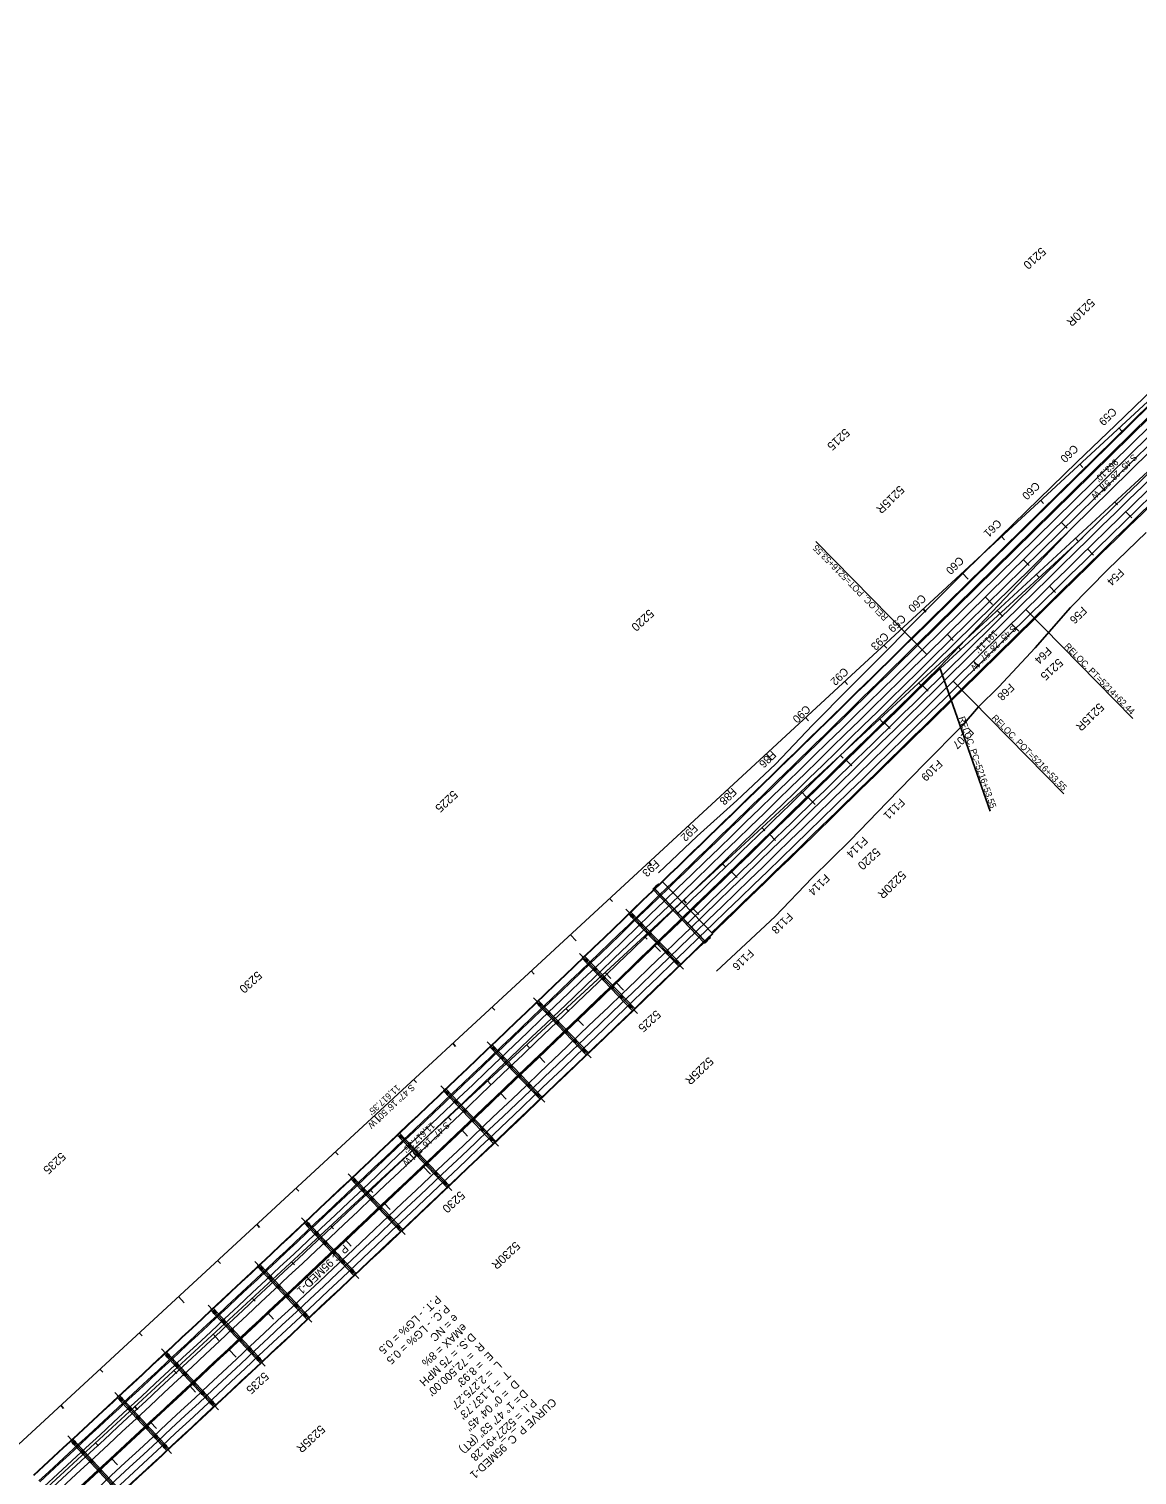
# Model space of a CAD drawing. Extents: x 2160877 to 2175861, y 601747 to 617724.
# Drawn here: x 2167267 to 2169344, y 609138 to 611848 of the extents above; entities that cross this region are included whole.
import ezdxf

# ---------------------------------------------------------------- set-up
doc = ezdxf.new("R2010")
doc.units = 0
for name, color, linetype in [('BR_CENTER LINES', 7, 'Continuous'), ('BR_CONCRETE', 7, 'Continuous'), ('RD_HC_Cl', 7, 'Continuous'), ('RD_HC_CL_Rel', 7, 'Continuous'), ('RD_HC_Data_Rel', 7, 'Continuous'), ('RD_HC_Data_Tic', 7, 'Continuous'), ('RD_HC_Data_Tic_Rel', 7, 'Continuous'), ('RD_HC_TX_Rel_Sta50', 7, 'Continuous'), ('RD_HC_TX_Rel_StaOther', 7, 'Continuous'), ('RD_HC_TX_StaOther', 7, 'Continuous'), ('RD_PD_CstnLmt', 7, 'Continuous'), ('RD_PD_CstnLmt_TX', 7, 'Continuous'), ('RD_PD_Final_LnLine', 7, 'Continuous'), ('RD_PD_Final_TrvlWay', 7, 'Continuous'), ('RD_PD_GR', 7, 'Continuous'), ('RD_PD_MedBWall', 7, 'Continuous')]:
    doc.layers.add(name, color=color, linetype=linetype)

msp = doc.modelspace()

# ---------------------------------------------------------------- linework, layer by layer
at = {"layer": 'BR_CENTER LINES'}
for p, q in [((2168386, 610198.5), (2168494.3, 610086.1)), ((2168299.5, 610115.4), (2168407.8, 610002.8)), ((2168213, 610032.5), (2168321, 609919.7)), ((2168126.4, 609949.7), (2168234.2, 609836.7)), ((2168039.6, 609867), (2168147.2, 609753.9)), ((2167964.2, 609772.3), (2168060.1, 609671.2)), ((2167865.6, 609702.1), (2167972.8, 609588.6)), ((2167778.4, 609619.9), (2167885.5, 609506.2)), ((2167691, 609537.8), (2167797.9, 609424)), ((2167603.6, 609455.9), (2167710.3, 609341.9)), ((2167515.9, 609374.1), (2167622.5, 609259.9)), ((2167428.2, 609292.4), (2167534.5, 609178.1)), ((2167340.3, 609210.9), (2167446.5, 609096.4))]:
    msp.add_line(p, q, dxfattribs=at)
at = {"layer": 'BR_CONCRETE'}
for p, q in [((2168436.5, 610235.6), (2168533.7, 610134.9)), ((2168439, 610238), (2168536.2, 610137.3)), ((2168439.6, 610236.4), (2168534.7, 610137.9)), ((2168447.3, 610246), (2168448.3, 610244.9)), ((2168454, 610250.3), (2168549, 610151.9)), ((2168543.4, 610146.4), (2168544.5, 610145.3))]:
    msp.add_line(p, q, dxfattribs=at)
for points in [[(2168394.9, 610193.2), (2168390.9, 610189.4), (2168485.4, 610091.4), (2168489.3, 610095.2)], [(2168308.4, 610110.1), (2168304.5, 610106.3), (2168398.8, 610008.1), (2168402.8, 610011.9)], [(2168221.9, 610027.1), (2168217.9, 610023.3), (2168312.1, 609925), (2168316.1, 609928.8)], [(2168135.3, 609944.3), (2168131.3, 609940.5), (2168225.3, 609842), (2168229.3, 609845.8)], [(2168048.5, 609861.7), (2168044.5, 609857.9), (2168138.3, 609759.2), (2168142.3, 609763)], [(2167961.5, 609779.1), (2167957.5, 609775.3), (2168051.2, 609676.5), (2168055.2, 609680.3)], [(2167874.4, 609696.7), (2167870.4, 609693), (2167964, 609594), (2167968, 609597.8)], [(2167787.2, 609614.5), (2167783.2, 609610.7), (2167876.6, 609511.6), (2167880.6, 609515.4)], [(2167699.9, 609532.4), (2167695.9, 609528.6), (2167789.1, 609429.4), (2167793.1, 609433.1)], [(2167612.4, 609450.4), (2167608.4, 609446.7), (2167701.4, 609347.3), (2167705.4, 609351)], [(2167524.8, 609368.6), (2167520.8, 609364.9), (2167613.6, 609265.3), (2167617.7, 609269.1)], [(2167437, 609287), (2167433, 609283.2), (2167525.7, 609183.5), (2167529.7, 609187.3)], [(2167349.1, 609205.5), (2167345.1, 609201.7), (2167437.7, 609101.8), (2167441.7, 609105.6)]]:
    msp.add_lwpolyline(points, close=True, dxfattribs=at)
for centre, radius in [((2168398, 610186.1), 2.5), ((2168414.3, 610169.1), 2.5), ((2168430.6, 610152.2), 2.5), ((2168446.9, 610135.3), 2.5), ((2168311.5, 610102.9), 2.5), ((2168464.2, 610117.3), 2.5), ((2168481.6, 610099.3), 2.5), ((2168327.8, 610086), 2.5), ((2168344.1, 610069), 2.5), ((2168360.4, 610052.1), 2.5), ((2168225, 610019.9), 2.5), ((2168377.7, 610034.1), 2.5), ((2168395, 610016), 2.5), ((2168241.3, 610003), 2.5), ((2168257.5, 609986), 2.5), ((2168273.8, 609969), 2.5), ((2168138.3, 609937.1), 2.5), ((2168291.1, 609951), 2.5), ((2168308.4, 609932.9), 2.5), ((2168154.6, 609920.1), 2.5), ((2168170.8, 609903.1), 2.5), ((2168187, 609886.1), 2.5), ((2168051.5, 609854.4), 2.5), ((2168204.3, 609868.1), 2.5), ((2168067.7, 609837.4), 2.5), ((2168221.5, 609850), 2.5), ((2168083.9, 609820.4), 2.5), ((2168100.1, 609803.4), 2.5), ((2167964.6, 609771.9), 2.5), ((2168117.3, 609785.3), 2.5), ((2167980.7, 609754.9), 2.5), ((2168134.6, 609767.2), 2.5), ((2167996.9, 609737.8), 2.5), ((2168013.1, 609720.8), 2.5), ((2167877.5, 609689.5), 2.5), ((2168030.3, 609702.6), 2.5), ((2167893.6, 609672.4), 2.5), ((2168047.5, 609684.5), 2.5), ((2167909.8, 609655.4), 2.5), ((2167925.9, 609638.3), 2.5), ((2167790.3, 609607.3), 3), ((2167790.3, 609607.3), 2), ((2167943.1, 609620.1), 2.5), ((2167806.4, 609590.2), 3), ((2167806.4, 609590.2), 2), ((2167960.3, 609602), 2.5), ((2167822.5, 609573.1), 3), ((2167822.5, 609573.1), 2), ((2167838.6, 609556), 3), ((2167838.6, 609556), 2), ((2167702.9, 609525.2), 3), ((2167855.7, 609537.8), 3), ((2167855.7, 609537.8), 2), ((2167702.9, 609525.2), 2), ((2167719, 609508), 3), ((2167719, 609508), 2), ((2167872.9, 609519.6), 3), ((2167872.9, 609519.6), 2), ((2167735.1, 609490.9), 3), ((2167735.1, 609490.9), 2), ((2167751.2, 609473.8), 3), ((2167751.2, 609473.8), 2), ((2167615.4, 609443.2), 3), ((2167768.3, 609455.6), 3), ((2167768.3, 609455.6), 2), ((2167615.4, 609443.2), 2), ((2167631.5, 609426.1), 3), ((2167631.5, 609426.1), 2), ((2167785.4, 609437.3), 3), ((2167785.4, 609437.3), 2), ((2167647.5, 609408.9), 3), ((2167647.5, 609408.9), 2), ((2167663.6, 609391.7), 3), ((2167663.6, 609391.7), 2), ((2167680.7, 609373.5), 3), ((2167680.7, 609373.5), 2), ((2167527.8, 609361.4), 3), ((2167527.8, 609361.4), 2), ((2167543.8, 609344.2), 3), ((2167543.8, 609344.2), 2), ((2167697.7, 609355.2), 3), ((2167697.7, 609355.2), 2), ((2167559.8, 609327), 3), ((2167559.8, 609327), 2), ((2167575.9, 609309.8), 3), ((2167575.9, 609309.8), 2), ((2167592.9, 609291.6), 3), ((2167592.9, 609291.6), 2), ((2167440, 609279.7), 3), ((2167440, 609279.7), 2), ((2167456, 609262.5), 3), ((2167456, 609262.5), 2), ((2167610, 609273.3), 3), ((2167610, 609273.3), 2), ((2167472, 609245.3), 3), ((2167472, 609245.3), 2), ((2167488, 609228.1), 3), ((2167488, 609228.1), 2), ((2167505, 609209.8), 3), ((2167505, 609209.8), 2), ((2167352.1, 609198.2), 3), ((2167352.1, 609198.2), 2), ((2167368.1, 609181), 3), ((2167368.1, 609181), 2), ((2167522.1, 609191.5), 3), ((2167522.1, 609191.5), 2), ((2167384, 609163.7), 3), ((2167384, 609163.7), 2), ((2167400, 609146.5), 3), ((2167400, 609146.5), 2)]:
    msp.add_circle(centre, radius, dxfattribs=at)
for centre, radius, start, end in [((2118143, 662346), 72423.5, 312.719474, 314.001577), ((2118143, 662346), 72438.5, 312.719474, 314.001576), ((2118143, 662346), 72440.8, 312.719474, 314.001576), ((2118136.1, 662361.9), 72438.1, 313.978709, 313.990573), ((2118136.1, 662361.9), 72439.6, 313.98095, 313.990573), ((2118143, 662346), 72498.8, 312.719474, 314.001574), ((2118143, 662346), 72501.2, 312.719474, 314.001574), ((2118143, 662346), 72559.2, 312.719474, 314.001572), ((2118143, 662346), 72560.2, 312.719474, 314.001572), ((2118143, 662346), 72560.3, 312.719474, 314.001572), ((2118147.4, 662350.2), 72561.9, 313.978713, 313.990557), ((2118147.4, 662350.2), 72560.4, 313.98095, 313.990557)]:
    msp.add_arc(centre, radius, start, end, dxfattribs=at)
at = {"layer": 'RD_HC_Cl'}
for p, q in [((2172207.3, 613775.1), (2163672.2, 605893.8)), ((2172272.5, 613704.6), (2163737.4, 605823.3))]:
    msp.add_line(p, q, dxfattribs=at)
at = {"layer": 'RD_HC_CL_Rel'}
for p, q in [((2169636.8, 611351.3), (2168950.1, 610676)), ((2169135.7, 610759.9), (2168999.4, 610625.9))]:
    msp.add_line(p, q, dxfattribs=at)
for centre, radius, start, end in [((2219616.9, 559421.3), 72000, 132.719474, 134.517591), ((2118143, 662346), 72500, 312.719474, 314.517591)]:
    msp.add_arc(centre, radius, start, end, dxfattribs=at)
at = {"layer": 'RD_HC_Data_Rel'}
for p, q in [((2168950.1, 610676), (2168742.3, 610887.4)), ((2169135.7, 610759.9), (2169336.4, 610555.8)), ((2168974.8, 610650.9), (2169069, 610382.3)), ((2168999.4, 610625.9), (2169207.3, 610414.5))]:
    msp.add_line(p, q, dxfattribs=at)
at = {"layer": 'RD_HC_Data_Tic'}
for p, q in [((2169310.6, 611100.3), (2169316, 611094.4)), ((2169237.1, 611032.5), (2169242.6, 611026.6)), ((2169163.7, 610964.6), (2169169.1, 610958.7)), ((2169302.3, 610961.9), (2169307.7, 610956.1)), ((2169090.2, 610896.8), (2169095.6, 610890.9)), ((2169228.8, 610894.1), (2169234.2, 610888.2)), ((2169016.7, 610828.9), (2169027.6, 610817.2)), ((2169155.3, 610826.3), (2169160.8, 610820.4)), ((2168943.3, 610761.1), (2168948.7, 610755.2)), ((2169081.9, 610758.4), (2169092.7, 610746.7)), ((2168869.8, 610693.3), (2168875.2, 610687.4)), ((2169008.4, 610690.6), (2169013.8, 610684.7)), ((2168796.3, 610625.4), (2168801.8, 610619.5)), ((2168934.9, 610622.7), (2168940.4, 610616.9)), ((2168722.9, 610557.6), (2168728.3, 610551.7)), ((2168861.5, 610554.9), (2168866.9, 610549)), ((2168649.4, 610489.7), (2168660.3, 610478)), ((2168788, 610487.1), (2168793.4, 610481.2)), ((2168575.9, 610421.9), (2168581.4, 610416)), ((2168714.5, 610419.2), (2168725.4, 610407.5)), ((2168502.5, 610354.1), (2168507.9, 610348.2)), ((2168641.1, 610351.4), (2168646.5, 610345.5)), ((2168429, 610286.2), (2168434.4, 610280.3)), ((2168567.6, 610283.5), (2168573, 610277.7)), ((2168355.5, 610218.4), (2168360.9, 610212.5)), ((2168494.1, 610215.7), (2168499.5, 610209.8)), ((2168282.1, 610150.5), (2168292.9, 610138.8)), ((2168420.6, 610147.8), (2168426.1, 610142)), ((2168208.6, 610082.7), (2168214, 610076.8)), ((2168347.2, 610080), (2168358, 610068.3)), ((2168135.1, 610014.9), (2168140.5, 610009)), ((2168273.7, 610012.2), (2168279.1, 610006.3)), ((2168061.6, 609947), (2168067.1, 609941.1)), ((2168200.2, 609944.3), (2168205.7, 609938.4)), ((2167988.2, 609879.2), (2167993.6, 609873.3)), ((2168126.8, 609876.5), (2168132.2, 609870.6)), ((2167914.7, 609811.3), (2167925.6, 609799.6)), ((2168053.3, 609808.6), (2168058.7, 609802.8)), ((2167841.2, 609743.5), (2167846.7, 609737.6)), ((2167979.8, 609740.8), (2167990.7, 609729)), ((2167767.8, 609675.6), (2167773.2, 609669.8)), ((2167906.4, 609673), (2167911.8, 609667.1)), ((2167694.3, 609607.8), (2167699.7, 609601.9)), ((2167832.9, 609605.1), (2167838.3, 609599.2)), ((2167620.8, 609540), (2167626.3, 609534.1)), ((2167759.4, 609537.3), (2167764.9, 609531.4)), ((2167547.4, 609472.1), (2167558.2, 609460.4)), ((2167686, 609469.4), (2167691.4, 609463.6)), ((2167473.9, 609404.3), (2167479.3, 609398.4)), ((2167612.5, 609401.6), (2167623.4, 609389.8)), ((2167400.4, 609336.4), (2167405.9, 609330.6)), ((2167539, 609333.8), (2167544.5, 609327.9)), ((2167327, 609268.6), (2167332.4, 609262.7)), ((2167465.6, 609265.9), (2167471, 609260)), ((2167392.1, 609198.1), (2167397.5, 609192.2))]:
    msp.add_line(p, q, dxfattribs=at)
at = {"layer": 'RD_HC_Data_Tic_Rel'}
for p, q in [((2169273.5, 610994), (2169284.7, 610982.6)), ((2169323.2, 610943.5), (2169334.3, 610932.1)), ((2169202.2, 610923.9), (2169213.4, 610912.5)), ((2169251.6, 610873.6), (2169262.8, 610862.2)), ((2169130.9, 610853.8), (2169142.1, 610842.4)), ((2169180.2, 610803.6), (2169191.4, 610792.2)), ((2169059.6, 610783.7), (2169073.6, 610769.4)), ((2169108.9, 610733.5), (2169122.9, 610719.3)), ((2168988.3, 610713.6), (2168999.5, 610702.2)), ((2169037.6, 610663.4), (2169048.8, 610652)), ((2168941.6, 610618.4), (2168952.8, 610607)), ((2168870.2, 610548.4), (2168881.4, 610536.9)), ((2168798.7, 610478.5), (2168809.9, 610467)), ((2168727.2, 610408.6), (2168741.1, 610394.3)), ((2168655.5, 610338.9), (2168666.6, 610327.4)), ((2168583.7, 610269.3), (2168594.8, 610257.8)), ((2168511.8, 610199.8), (2168522.9, 610188.3)), ((2168439.8, 610130.3), (2168450.9, 610118.8)), ((2168367.8, 610061), (2168381.6, 610046.6)), ((2168295.6, 609991.8), (2168306.7, 609980.2)), ((2168223.3, 609922.7), (2168234.4, 609911.1)), ((2168151, 609853.6), (2168162, 609842)), ((2168078.5, 609784.7), (2168089.6, 609773.1)), ((2168006, 609715.9), (2168019.7, 609701.4)), ((2167933.4, 609647.2), (2167944.3, 609635.5)), ((2167860.6, 609578.5), (2167871.6, 609566.9)), ((2167787.8, 609510), (2167798.7, 609498.3)), ((2167714.9, 609441.6), (2167725.8, 609429.9)), ((2167641.8, 609373.3), (2167655.5, 609358.6)), ((2167568.7, 609305), (2167579.6, 609293.3)), ((2167495.5, 609236.9), (2167506.4, 609225.2)), ((2167422.2, 609168.9), (2167433.1, 609157.1))]:
    msp.add_line(p, q, dxfattribs=at)
at = {"layer": 'RD_PD_CstnLmt'}
for p, q in [((2169375.9, 611175.1), (2169303.7, 611105.9)), ((2169303.7, 611105.9), (2169231.7, 611036.5)), ((2169231.7, 611036.5), (2169159.9, 610966.9)), ((2169159.9, 610966.9), (2169088.4, 610897)), ((2169088.4, 610897), (2169017.2, 610826.8)), ((2169361.1, 610904.6), (2169289.3, 610835.1)), ((2169289.3, 610835.1), (2169219.5, 610763.6)), ((2169017.2, 610826.8), (2168946.4, 610756.1)), ((2168946.4, 610756.1), (2168908.6, 610718.2)), ((2169219.5, 610763.6), (2169153.6, 610688.1)), ((2168909.1, 610717.7), (2168876.5, 610684.8)), ((2168876.5, 610684.8), (2168806, 610613.9)), ((2169153.6, 610688.1), (2169085, 610615.2)), ((2168806, 610613.9), (2168735.7, 610543.1)), ((2169085, 610615.2), (2169047, 610577.5)), ((2169047, 610577.5), (2169016.7, 610542)), ((2168735.7, 610543.1), (2168666.9, 610470.5)), ((2169016.7, 610542), (2168946.2, 610470.8)), ((2168666.9, 610470.5), (2168594.2, 610402)), ((2168946.2, 610470.8), (2168876.1, 610399.2)), ((2168594.2, 610402), (2168519.6, 610335.4)), ((2168876.1, 610399.2), (2168806.6, 610327)), ((2168519.6, 610335.4), (2168447.1, 610266.8)), ((2168806.6, 610327), (2168735.1, 610256.9)), ((2168735.1, 610256.9), (2168665.8, 610184.6)), ((2168665.8, 610184.6), (2168556.1, 610081.9))]:
    msp.add_line(p, q, dxfattribs=at)
at = {"layer": 'RD_PD_Final_LnLine'}
for p, q in [((2168941.7, 610684.6), (2169628.4, 611359.8)), ((2168958.5, 610667.5), (2169645.3, 611342.7)), ((2169219.5, 610910), (2168973.9, 610651.8)), ((2168975.6, 610650.1), (2169242.4, 610895.4)), ((2168991, 610634.4), (2169127.3, 610768.4)), ((2169007.8, 610617.3), (2169144.1, 610751.3))]:
    msp.add_line(p, q, dxfattribs=at)
for centre, radius, start, end in [((2219616.9, 559421.3), 72012, 132.719474, 134.517591), ((2219616.9, 559421.3), 71988, 132.719474, 134.517591), ((2118143, 662346), 72452.8, 312.719474, 314.517591), ((2118143, 662346), 72464.8, 312.719474, 314.517591), ((2118143, 662346), 72476.8, 312.719474, 314.517591), ((2118143, 662346), 72498.8, 312.719474, 314.517591), ((2118143, 662346), 72501.2, 312.719474, 314.517591), ((2118143, 662346), 72523.2, 312.719474, 314.517591), ((2118143, 662346), 72535.2, 312.719474, 314.517591), ((2118143, 662346), 72547.2, 312.719474, 314.517591)]:
    msp.add_arc(centre, radius, start, end, dxfattribs=at)
at = {"layer": 'RD_PD_Final_TrvlWay'}
for p, q in [((2168931.7, 610694.8), (2169618.4, 611370.1)), ((2168933.3, 610693.2), (2169620.1, 611368.4)), ((2168965.5, 610660.3), (2169652.3, 611335.6)), ((2168984, 610641.6), (2169120.3, 610775.6)), ((2169014.8, 610610.2), (2169151.1, 610744.2))]:
    msp.add_line(p, q, dxfattribs=at)
for centre, radius, start, end in [((2219616.9, 559421.3), 72022, 132.719474, 134.517591), ((2219616.9, 559421.3), 71978, 132.719474, 134.517591), ((2118141.6, 662347.5), 72440.5, 314.001541, 314.517591), ((2118141.6, 662347.5), 72442.8, 314.001541, 314.517591), ((2118143, 662346), 72486.8, 313.983529, 314.517591), ((2118143, 662346), 72513.2, 313.98353, 314.517591), ((2118143, 662346), 72557.2, 314.001574, 314.517591)]:
    msp.add_arc(centre, radius, start, end, dxfattribs=at)
at = {"layer": 'RD_PD_GR'}
msp.add_line((2169016.3, 610608.8), (2169152.5, 610742.8), dxfattribs=at)
for centre, radius, start, end in [((2219616.9, 559421.3), 71976, 132.719474, 134.517591), ((2118143, 662346), 72559.2, 313.996755, 314.517591)]:
    msp.add_arc(centre, radius, start, end, dxfattribs=at)
at = {"layer": 'RD_PD_MedBWall'}
for p, q in [((2168921.2, 610705.5), (2169607.9, 611380.8)), ((2168921.9, 610704.8), (2169608.6, 611380.1))]:
    msp.add_line(p, q, dxfattribs=at)
for centre, radius, start, end in [((2118141.6, 662347.5), 72425.5, 314.001541, 314.517591), ((2118141.6, 662347.5), 72426.5, 314.001541, 314.517591), ((2118142.8, 662346.1), 72424.7, 312.719474, 314.001577)]:
    msp.add_arc(centre, radius, start, end, dxfattribs=at)

# ---------------------------------------------------------------- texts
at = {"layer": 'RD_HC_Data_Rel'}
for s, height, rotation, p in [('RELOC. POT=5216+53.55', 12, 134.5176, (2168878.6, 610745.9)), ('RELOC. PT=5214+62.44', 12, 314.5176, (2169207.2, 610690)), ('RELOC. PC=5216+53.55', 12, 289.3225, (2169009.7, 610557.2)), ('RELOC. POT=5216+53.55', 12, 314.5176, (2169071, 610556)), ('P C 95MED-1', 15, 223.5528, (2167858, 609570.9)), ('P.T. - LG% = 0.5', 15, 222.7195, (2168031.6, 609475.6)), ('P.C. - LG% = 0.5', 15, 222.7195, (2168047.9, 609458)), ('eMAX = 8%', 15, 222.7195, (2168080.4, 609422.7)), ('e = NC', 15, 222.7195, (2168064.1, 609440.3)), ('D.S. = 75 MPH', 15, 222.7195, (2168096.7, 609405.1)), ("R  = 72,500.00'", 15, 222.7195, (2168113, 609387.4)), ("E  = 8.93'", 15, 222.7195, (2168129.3, 609369.8)), ("L  = 2,275.27'", 15, 222.7195, (2168145.6, 609352.2)), ("T  = 1,137.73'", 15, 222.7195, (2168161.8, 609334.5)), ('D  = 0%%d 04\' 45"', 15, 222.7195, (2168178.1, 609316.9)), ('   = 1%%d 47\' 53" (RT)', 15, 222.7195, (2168194.4, 609299.3)), ('D ', 15, 222.7195, (2168194.4, 609299.3)), ('CURVE P_C_95MED-1', 15, 222.7195, (2168247.6, 609283)), ('P.I. = 5227+91.28', 15, 222.7195, (2168210.7, 609281.6))]:
    msp.add_text(s, height=height, rotation=rotation, dxfattribs=at).set_placement(p)
at = {"layer": 'RD_HC_TX_Rel_Sta50'}
for s, rotation, p in [('5210R', 224.5176, (2169255.7, 611344.6)), ('5215R', 224.5176, (2168898.9, 610993.8)), ('5215R', 224.5176, (2169273.2, 610586.2)), ('5220R', 224.2438, (2168902, 610271.8)), ('5225R', 223.8487, (2168541.4, 609922.7)), ('5230R', 223.4535, (2168178.9, 609576.6)), ('5235R', 223.0584, (2167813.5, 609232.6))]:
    msp.add_text(s, height=16, rotation=rotation, dxfattribs=at).set_placement(p)
at = {"layer": 'RD_HC_TX_Rel_StaOther'}
for s, p in [('S 45%%d 28\' 57" W', (2169337.4, 611052.6)), ("963.10'", (2169302.1, 611043.2)), ('S 45%%d 28\' 57" W', (2169111.5, 610731.8)), ("191.11'", (2169076.2, 610722.4))]:
    msp.add_text(s, height=12, rotation=224.5176, dxfattribs=at).set_placement(p)
at = {"layer": 'RD_HC_TX_StaOther'}
for s, height, p in [('5210', 16, (2169164.6, 611440.3)), ('5215', 16, (2168796.9, 611100.7)), ('5220', 16, (2168429.9, 610761.8)), ('5215', 16, (2169196.7, 610669.6)), ('5225', 16, (2168062.2, 610422.3)), ('5220', 16, (2168854.2, 610314.6)), ('5230', 16, (2167695.2, 610083.4)), ('5225', 16, (2168442.7, 610010.3)), ('S 47%%d 16\' 50" W', 12, (2167984, 609871.2)), ("11,617.35'", 12, (2167956.6, 609870.4)), ('S 47%%d 16\' 50" W', 12, (2168049.1, 609800.7)), ("11,617.35'", 12, (2168021.7, 609799.9)), ('5235', 16, (2167327.5, 609743.9)), ('5230', 16, (2168075.7, 609671.4)), ('5235', 16, (2167708, 609331.9))]:
    msp.add_text(s, height=height, rotation=222.7195, dxfattribs=at).set_placement(p)
at = {"layer": 'RD_PD_CstnLmt_TX'}
for s, rotation, p in [('C59', 224.5176, (2169297.4, 611139.8)), ('C60', 224.5176, (2169225.4, 611070.4)), ('C60', 224.5176, (2169153.6, 611000.8)), ('C61', 224.5176, (2169081.6, 610930.4)), ('C60', 224.5176, (2169010.9, 610860.7)), ('F54', 224.3883, (2169311.2, 610838.2)), ('C60', 224.5176, (2168940.1, 610790)), ('C59', 224.5176, (2168902.3, 610752.1)), ('F56', 224.4679, (2169241.5, 610766.8)), ('C93', 224.4809, (2168870.2, 610718.6)), ('F64', 224.5176, (2169175.4, 610691.2)), ('C92', 224.4019, (2168794.6, 610652.6)), ('F68', 224.5176, (2169105.6, 610622.8)), ('C90', 224.3228, (2168723.5, 610582.2)), ('F107', 224.4809, (2169029.6, 610540)), ('F86', 224.2438, (2168659.1, 610496.6)), ('F109', 224.4019, (2168970.9, 610479.5)), ('F88', 224.1648, (2168585.1, 610426.9)), ('F111', 224.3228, (2168900.3, 610407.4)), ('F92', 224.0857, (2168512.3, 610358.8)), ('F114', 224.2438, (2168831.1, 610335.5)), ('F93', 224.0067, (2168440.4, 610292.3)), ('F114', 224.1648, (2168759.7, 610265.3)), ('F118', 224.0857, (2168690.5, 610193.1)), ('F116', 224.0067, (2168617.3, 610124.5))]:
    msp.add_text(s, height=15, rotation=rotation, dxfattribs=at).set_placement(p)

doc.saveas('drawing.dxf')
